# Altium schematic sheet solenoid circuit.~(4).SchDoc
size A; SheetNumber: 1; SheetTotal: 1
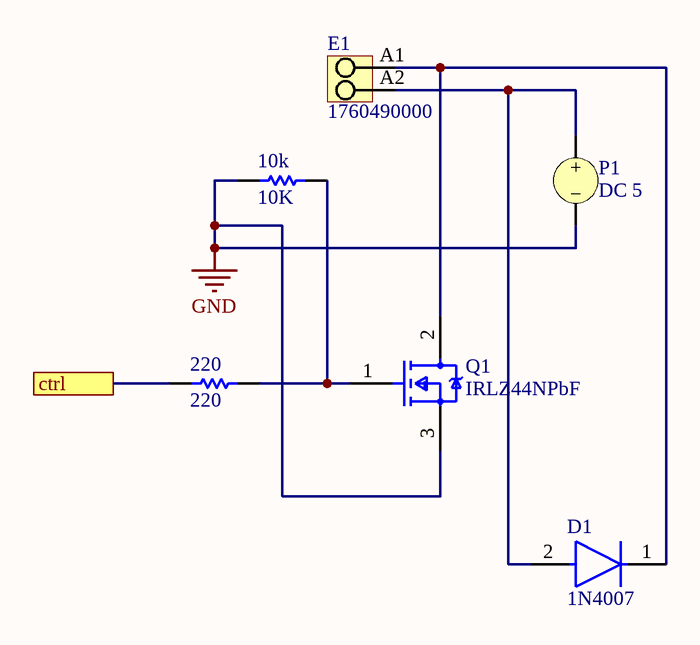
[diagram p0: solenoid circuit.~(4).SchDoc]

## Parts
10k  value 10K  (hidden comment: Resistor)
220  value 220  (hidden comment: Resistor)
D1  1N4007  [FP-1N4007-MFG]
E1  1760490000  [PM_5_08_90_02]
P1  DC 5
Q1  IRLZ44NPbF  [FP-PG-TO220-3-MFG]

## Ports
ctrl

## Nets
GND: 10k.1 P1.2 Q1.3(S)
ctrl: 220.1 ; port ctrl
Net10k_2: 10k.2 220.2 Q1.1(G)
NetD1_1: D1.1(C) E1.A1 Q1.2(D)
NetD1_2: D1.2(A) E1.A2 P1.1

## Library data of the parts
10k 220 = Resistor: TC1: 0; SimulationGenericComponent: True
D1 = CMP-123542-000001-1: Rectifier diode 1000 V 1 A DO-41, ,; Manufacturer: Diotec; Max Surge Forward Current: 27A; Forward Current: 1A; Max Junction Temp: +175°C; Reverse Voltage: 1000V; Value: 15pF; Peak Reverse Current: 5uA
E1 = CMP-1559-01627-1: OMNIMATE Signal - series PM; Manufacturer: Weidmueller; Contact_surface: tinned; Pitch_mm: 5,08 mm; Solid_min_H05_07_V_U: 0,13 mm²; Wire_cross_section_AWG_min_UL_1059: AWG 26; Wire_cross_section_AWG_max_UL_1059: AWG 14; Rated_voltage_for_surge_voltage_class_pollution_degree_II_2: 600 V; Rated_current_use_group_B_UL_1059: 15 A; Mounting_onto_the_PCB: Solder connection; Solder_pin_length_mm: 3,5 mm; Side_termination_characteristic: closed side; Contact_material: Cu-Leg; Pitch_inch: 0,2 inch; No_of_poles: 2; UL_94_flammability_rating: V-0; Insulating_material: Wemid (PA); Rated_voltage_use_group_B_UL_1059: 300 V; Solid_max_H05_07_V_U: 2,5 mm²; Short_text_for_material: PM 5.08/02/90 3.5SN OR BX
P1 = VSRC: Voltage Source; Note: PCB Footprint - Not required; AC Magnitude: 1; AC Phase: 0; Value: 5
Q1 = CMP-32901-000488-1: MOSFET N-CH 55V 47A TO220AB; Turn-On Delay Time: 11ns; Gate to Source Voltage (Vgs): 16V; Element Configuration: Single; Rds On Max: 22mR; Turn-Off Delay Time: 26ns; Max Power Dissipation: 110W; Threshold Voltage: 2V; Drain to Source Resistance: 35mR; Input Capacitance: 1.7nF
